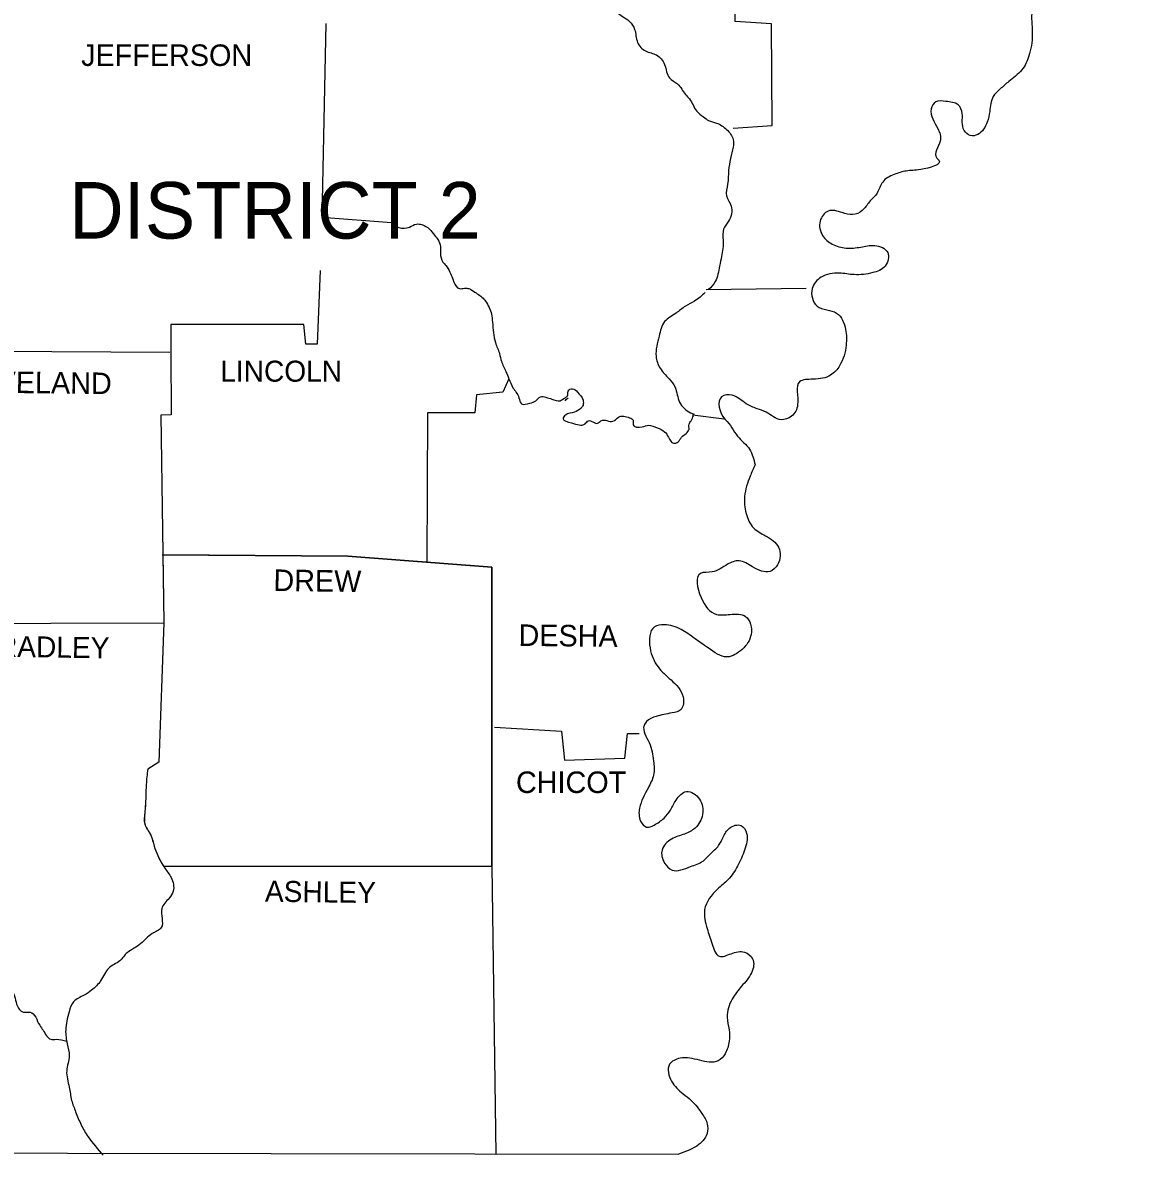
# Model space of a CAD drawing. Extents: x -42408 to 34530, y -43140 to 20491.
# Drawn here: x 3155 to 4265, y -35714 to -34581 of the extents above; entities that cross this region are included whole.
import ezdxf

# ---------------------------------------------------------------- set-up
doc = ezdxf.new("R2010")
doc.units = 0
for name, color, linetype in [('1', 7, 'Continuous'), ('2', 7, 'Continuous'), ('3', 7, 'Continuous'), ('S_MISC_BOUNDARY', 7, 'Continuous')]:
    doc.layers.add(name, color=color, linetype=linetype)

msp = doc.modelspace()

# ---------------------------------------------------------------- linework, layer by layer
at = {"layer": '1'}
msp.add_line((3839, -34847.9), (3939.1, -34846.4), dxfattribs=at)
for points in [[(3866, -34686.2), (3905, -34683.7), (3904.5, -34582), (3868, -34579.5), (3870, -34380.8), (3838.5, -34376.2), (3837.5, -34242.6), (4264.5, -34239.6)], [(3458.4, -34581.5), (3454.4, -34775.3), (3524, -34780.8)], [(3452.9, -34828.8), (3449.9, -34902.4), (3438.4, -34902.4), (3436.4, -34882.9), (3303.2, -34882.9), (3303.2, -34911)], [(3125, -34909.5), (3302.2, -34910.5)], [(3303.2, -34910.5), (3303.7, -34973), (3293.2, -34973.5), (3296.2, -35181.3)], [(3641.7, -34937), (3635.7, -34950.5), (3609.1, -34953), (3607.6, -34971), (3560.1, -34971), (3559.6, -35120.7)], [(3697.8, -34959), (3699.3, -34957.5), (3700.8, -34956), (3700.8, -34956)], [(3294.7, -35113.2), (3480.5, -35114.7), (3624.7, -35125.7)], [(3624.7, -35125.7), (3624.7, -35425.1), (3628.7, -35713)], [(3069.9, -35181.8), (3296.2, -35181.3)], [(3296.2, -35181.3), (3291.2, -35320.5), (3280.2, -35327.5)], [(3627.2, -35285.5), (3694.3, -35289.5), (3697.3, -35318.5), (3757.8, -35316.5), (3760.3, -35292), (3771.9, -35292)], [(1975.5, -35305), (1976.5, -35710), (3811.4, -35713)], [(3299.2, -35424.6), (3624.7, -35424.6)]]:
    msp.add_lwpolyline(points, dxfattribs=at)
for points in [[(4233, -34360.7), (4221.5, -34375.2), (4204.4, -34366.2), (4204.4, -34354.2), (4206.9, -34341.7), (4200.9, -34333.7), (4190.4, -34337.2), (4190.4, -34352.7), (4189.4, -34367.7), (4186.4, -34389.3), (4193.4, -34395.8), (4209.4, -34397.8), (4221, -34400.8), (4228, -34412.3), (4227.5, -34426.3), (4222, -34439.8), (4214, -34450.8), (4201.4, -34454.9), (4191.4, -34448.3), (4187.4, -34435.3), (4182.9, -34423.8), (4174.4, -34415.3), (4165.4, -34424.8), (4163.4, -34442.3), (4163.9, -34457.4), (4163.9, -34477.9), (4176.9, -34491.4), (4184.9, -34506.9), (4182.4, -34520.9), (4172.9, -34537.5), (4168.9, -34552), (4164.9, -34571.5), (4165.4, -34593), (4161.9, -34614.1), (4154.9, -34628.1), (4141.9, -34639.6), (4133.3, -34647.1), (4126.3, -34654.6), (4122.8, -34669.6), (4120.3, -34680.2), (4110.8, -34692.7), (4103.3, -34693.7), (4097.3, -34688.7), (4095.3, -34680.2), (4095.3, -34671.6), (4091.3, -34663.1), (4078.8, -34659.6), (4068.8, -34660.1), (4064.3, -34667.1), (4070.8, -34686.7), (4073.3, -34699.2), (4069.8, -34716.2), (4071.8, -34718.2), (4053.7, -34727.7), (4039.2, -34729.2), (4027.2, -34732.7), (4015.7, -34740.2), (4010.2, -34751.2), (4002.2, -34760.3), (3995.2, -34768.8), (3985.6, -34772.8), (3975.1, -34770.8), (3961.1, -34769.3), (3953.1, -34779.3), (3955.6, -34793.8), (3965.1, -34802.3), (3979.1, -34806.3), (3993.7, -34805.3), (4007.7, -34803.8), (4020.7, -34810.8), (4018.2, -34824.3), (4005.7, -34830.9), (3987.2, -34832.9), (3972.1, -34831.4), (3954.1, -34835.4), (3945.1, -34846.9), (3950.1, -34864.4), (3969.6, -34871.4), (3978.6, -34887.9), (3979.1, -34903.4), (3972.6, -34924), (3963.6, -34933.5), (3946.1, -34937.5), (3932.6, -34940), (3930.6, -34963), (3924.6, -34974.5), (3914.1, -34978), (3899, -34970.5), (3890, -34967), (3879, -34962), (3865, -34953.5), (3854.5, -34955), (3857.5, -34977), (3858.5, -34978), (3870.5, -34994.6), (3882.5, -35007.6), (3888, -35023.1)], [(3714.3, -34521.9), (3715.8, -34542.5), (3727.8, -34545.5), (3732.8, -34551), (3735.3, -34562.5), (3743.8, -34567.5), (3755.3, -34574.5), (3762.4, -34579.5), (3767.4, -34587.5), (3770.4, -34600.5), (3778.4, -34609.1), (3789.4, -34613.1), (3797.4, -34622.6), (3802.4, -34636.1), (3810.4, -34642.1), (3818.4, -34652.6), (3822.4, -34657.1), (3829.4, -34669.1), (3836.4, -34675.1), (3841.5, -34678.6), (3849.5, -34681.2), (3859.5, -34687.7), (3866, -34697.7), (3866, -34705.2), (3863.5, -34716.7), (3861.5, -34728.7), (3860.5, -34742.2), (3859.5, -34754.2), (3864, -34764.3), (3861.5, -34779.3), (3856.5, -34787.3), (3856, -34798.3), (3854.5, -34814.8), (3852.5, -34824.3), (3848, -34839.9), (3841.5, -34847.9)], [(3524, -34780.8), (3531.5, -34785.8), (3542.1, -34785.3), (3549.1, -34782.3), (3554.6, -34782.8), (3562.1, -34787.3), (3567.1, -34793.3), (3570.6, -34797.8), (3573.1, -34804.8), (3573.1, -34811.3), (3575.6, -34820.3), (3578.6, -34823.8), (3582.6, -34830.4), (3585.1, -34836.4), (3586.6, -34840.4), (3592.1, -34846.9), (3597.1, -34846.4), (3601.6, -34846.9), (3607.6, -34850.4), (3616.7, -34857.4), (3618.2, -34859.4), (3624.2, -34872.4), (3625.2, -34880.4), (3626.2, -34890.9), (3628.2, -34900.9), (3632.2, -34912), (3634.2, -34919.5), (3638.7, -34930), (3641.7, -34937), (3645.7, -34946), (3651.7, -34956), (3654.2, -34962), (3662.7, -34961.5), (3668.7, -34959), (3673.2, -34955), (3678.7, -34955.5), (3684.7, -34957.5), (3692.8, -34959), (3697.8, -34956), (3700.3, -34954), (3700.8, -34949.5), (3705.3, -34947), (3710.3, -34950.5), (3715.8, -34958.5), (3715.8, -34963.5), (3713.8, -34966.5), (3707.3, -34970.5), (3698.3, -34973.5), (3695.8, -34977), (3704.3, -34981.1), (3717.8, -34982.1), (3721.3, -34979), (3730.3, -34981.6), (3733.8, -34979), (3745.8, -34979.6), (3751.3, -34975.5), (3762.4, -34976), (3765.9, -34978.5), (3765.9, -34983.1), (3774.9, -34985.1), (3781.4, -34983.6), (3789.9, -34986.1), (3797.4, -34990.1), (3801.4, -34995.6), (3806.4, -35001.6), (3810.9, -35000.1), (3814.4, -34995.6), (3821.9, -34987.6), (3821.9, -34982.6), (3823.9, -34979), (3826.4, -34974)], [(3838, -34850.9), (3827.4, -34859.4), (3818.4, -34864.4), (3808.9, -34871.4), (3797.4, -34879.9), (3791.9, -34894.4), (3788.9, -34914.5), (3792.9, -34926.5), (3801.9, -34937), (3807.9, -34945.5), (3812.4, -34960.5), (3823.4, -34971), (3826.9, -34972.5)], [(3888, -35023.1), (3883, -35034.6), (3877.5, -35054.7), (3879, -35071.7), (3886.5, -35086.2), (3898.5, -35094.2), (3911.5, -35105.7), (3910.5, -35123.2), (3903, -35129.8), (3885.5, -35125.2), (3872, -35119.2), (3860.5, -35122.7), (3845, -35130.3), (3833.4, -35131.8), (3833.9, -35155.8), (3849.5, -35172.8), (3863, -35172.8), (3878.5, -35174.8), (3884, -35192.8), (3875, -35207.9), (3860, -35215.4), (3841, -35206.4), (3827.4, -35196.8), (3813.9, -35187.8), (3796.9, -35183.3), (3787.4, -35185.3), (3782.9, -35206.4), (3790.9, -35225.4), (3803.9, -35238.4), (3815.9, -35255.4), (3813.9, -35267.9), (3804.9, -35271.4), (3788.9, -35274.9), (3779.4, -35280), (3776.9, -35284), (3781.9, -35301), (3786.4, -35319.5), (3786.4, -35333.5), (3780.9, -35346.5), (3772.4, -35366.6), (3773.4, -35379.6), (3779.4, -35385.6), (3786.9, -35383.6), (3796.9, -35376.6), (3803.4, -35368.6), (3808.9, -35358.6), (3819.4, -35350), (3832.4, -35357.6), (3835.4, -35373.1), (3827.9, -35386.6), (3817.4, -35392.6), (3804.4, -35397.6), (3794.9, -35408.6), (3797.4, -35421.6), (3804.9, -35428.6), (3823.4, -35425.1), (3835.9, -35419.6), (3843, -35412.6), (3851.5, -35404.1), (3856, -35395.6), (3862.5, -35386.6), (3874, -35384.1), (3879.5, -35391.6), (3877.5, -35408.6), (3870.5, -35424.6), (3861, -35438.2), (3850.5, -35447.7), (3837.5, -35468.2), (3840, -35487.2), (3845, -35502.7), (3852, -35514.8), (3864, -35512.3), (3877.5, -35510.8), (3885.5, -35517.3), (3884.5, -35531.3), (3874.5, -35544.8), (3865, -35557.8), (3860, -35575.8), (3862, -35588.4), (3862, -35599.9), (3858, -35612.4), (3851, -35619.4), (3832.4, -35618.9), (3812.9, -35616.9), (3802.4, -35622.9), (3804.4, -35639.9), (3815.9, -35652.4), (3823.9, -35659), (3835.4, -35673), (3840.5, -35684.5), (3839, -35694.5), (3831.9, -35703), (3811.4, -35713)], [(3280.2, -35327.5), (3278.7, -35343), (3278.2, -35357.6), (3277.2, -35371.6), (3277.2, -35382.1), (3283.2, -35393.6), (3286.7, -35404.6), (3290.2, -35414.1), (3297.2, -35426.6), (3303.7, -35436.2), (3305.7, -35449.7), (3301.7, -35456.7), (3294.2, -35467.2), (3293.7, -35486.2), (3284.7, -35492.2), (3273.2, -35502.2), (3266.7, -35506.8), (3259.7, -35511.3), (3252.2, -35519.3), (3241.2, -35526.8), (3233.1, -35539.3), (3224.1, -35548.8), (3216.6, -35553.8), (3206.1, -35560.3), (3201.6, -35570.3), (3198.1, -35588.9), (3199.6, -35602.4), (3201.6, -35614.4), (3199.1, -35629.4), (3201.6, -35645.9), (3204.1, -35659), (3208.1, -35670.5), (3213.6, -35683.5), (3220.6, -35695.5), (3235.6, -35714)], [(2781, -35443.2), (2789.1, -35437.7), (2796.6, -35434.7), (2804.1, -35436.2), (2812.1, -35437.2), (2819.1, -35436.2), (2828.1, -35437.7), (2835.6, -35442.2), (2844.1, -35445.7), (2852.6, -35445.7), (2860.1, -35445.7), (2866.7, -35450.2), (2878.7, -35449.7), (2888.7, -35445.7), (2898.7, -35442.7), (2912.2, -35441.2), (2924.2, -35449.7), (2932.7, -35456.7), (2939.8, -35464.7), (2944.8, -35473.7), (2950.3, -35478.7), (2959.3, -35482.2), (2966.3, -35483.7), (2974.8, -35486.2), (2979.3, -35488.2), (2983.3, -35497.7), (2989.8, -35510.8), (3002.3, -35515.3), (3017.9, -35509.3), (3030.4, -35505.8), (3039.4, -35502.7), (3044.9, -35500.7), (3049.9, -35500.2), (3048.4, -35499.2), (3054.4, -35497.7), (3059.9, -35501.7), (3063.4, -35507.3), (3069.4, -35515.3), (3074.9, -35522.3), (3080.4, -35524.8), (3085.9, -35521.8), (3093.5, -35524.3), (3100, -35526.8), (3107.5, -35528.8), (3114, -35529.3), (3122.5, -35531.3), (3129, -35534.8), (3135, -35538.3), (3141, -35544.8), (3147, -35554.8), (3149, -35562.8), (3156, -35570.8), (3162.6, -35570.8), (3172.1, -35583.9), (3175.6, -35588.9), (3183.1, -35597.9), (3188.6, -35597.9), (3199.1, -35599.9)]]:
    msp.add_spline(points, degree=3, dxfattribs=at)
at = {"layer": '3'}
msp.add_line((3825.4, -34973), (3857, -34977), dxfattribs=at)
at = {"layer": 'S_MISC_BOUNDARY'}
for p, q in [((3295.2, -35113.2), (3296.2, -35181.3)), ((3624.7, -35424.6), (3624.7, -35125.7)), ((3296, -35424.6), (3624.7, -35424.6))]:
    msp.add_line(p, q, dxfattribs=at)
for points in [[(3624.7, -35125.7), (3480.5, -35114.7), (3295.2, -35113.2)], [(3296.2, -35181.3), (3291.2, -35320.5), (3280.2, -35327.5)]]:
    msp.add_lwpolyline(points, dxfattribs=at)
msp.add_spline([(3280.2, -35327.5), (3278.7, -35343), (3278.2, -35357.6), (3277.2, -35371.6), (3276.9, -35376.8), (3277, -35379.5), (3277.2, -35382.1), (3278.2, -35385.1), (3279.9, -35387.9), (3281.8, -35390.7), (3283.2, -35393.6), (3286.7, -35404.6), (3290.2, -35414.1), (3296, -35424.6)], degree=3, dxfattribs=at)

# ---------------------------------------------------------------- texts
at = {"layer": '2'}
for s, height, p in [('JEFFERSON', 21.53, (3213.6, -34624.1)), ('LINCOLN', 21.03, (3352.8, -34940)), ('CHICOT', 21.53, (3648.7, -35351.5))]:
    msp.add_text(s, height=height, dxfattribs=at).set_placement(p)
for s, height, rotation, p in [('CLEVELAND', 21.53, 359.3377, (3072.9, -34950.5)), ('DREW', 21.52, 359.2258, (3405.9, -35149.3)), ('DESHA', 21.52, 359.3704, (3651.2, -35204.3)), ('BRADLEY', 21.02, 359.1449, (3110.5, -35214.9)), ('ASHLEY', 21.03, 359.2361, (3397.4, -35460.2))]:
    msp.add_text(s, height=height, rotation=rotation, dxfattribs=at).set_placement(p)
at = {"layer": '3'}
msp.add_text('DISTRICT 2', height=56.57, dxfattribs=at).set_placement((3201.6, -34796.8))

doc.saveas('drawing.dxf')
